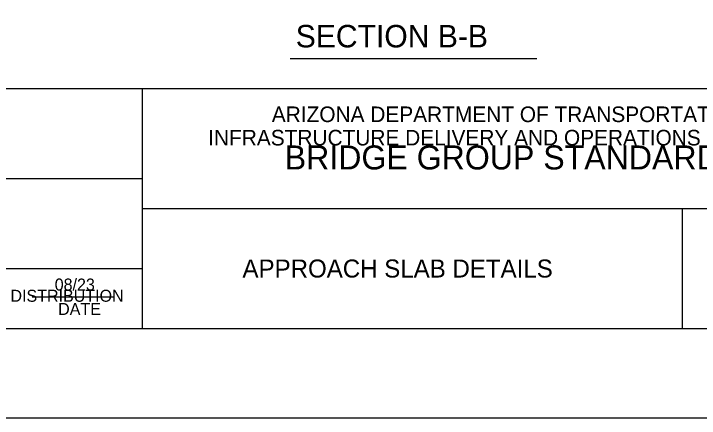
# Model space of a CAD drawing. Extents: x 0 to 2.83, y -0.03 to 1.83.
# Drawn here: x 2.0982 to 2.5744, y 0 to 0.2812 of the extents above; entities that cross this region are included whole.
import ezdxf

# ---------------------------------------------------------------- set-up
doc = ezdxf.new("R2010")
doc.units = 0
for name, color, linetype in [('57', 7, 'Continuous'), ('62', 7, 'Continuous'), ('63', 7, 'Continuous')]:
    doc.layers.add(name, color=color, linetype=linetype)

msp = doc.modelspace()

# ---------------------------------------------------------------- linework, layer by layer
at = {"layer": '57'}
msp.add_line((2.29027, 0.25017), (2.4616, 0.25017), dxfattribs=at)
at = {"layer": '62'}
for p, q in [((2.72918, 0.22911), (1.85418, 0.22911)), ((2.72918, 0.22911), (1.85418, 0.22911)), ((2.72918, 0.22911), (1.85418, 0.22911)), ((2.18751, 0.22911), (2.18751, 0.06244)), ((2.18751, 0.22911), (2.18751, 0.06244)), ((2.18751, 0.22911), (2.18751, 0.06244)), ((1.85418, 0.16661), (2.18751, 0.16661)), ((2.18751, 0.14578), (2.72918, 0.14578)), ((2.56251, 0.14578), (2.56251, 0.06244)), ((2.56251, 0.14578), (2.56251, 0.06244)), ((2.56251, 0.14578), (2.56251, 0.06244)), ((1.85418, 0.10411), (2.18751, 0.10411)), ((2.11099, 0.08432), (2.16752, 0.08432)), ((2.11099, 0.08432), (2.16752, 0.08432)), ((2.11099, 0.08432), (2.16752, 0.08432))]:
    msp.add_line(p, q, dxfattribs=at)
msp.add_lwpolyline([(2.72918, 1.77077), (0.10418, 1.77077), (0.10418, 0.06244), (2.72918, 0.06244)], close=True, dxfattribs=at)
at = {"layer": '63'}
for p, q in [((1.85418, 0.16661), (2.18751, 0.16661)), ((1.85418, 0.16661), (2.18751, 0.16661)), ((2.18751, 0.14578), (2.72918, 0.14578)), ((2.18751, 0.14578), (2.72918, 0.14578)), ((1.85418, 0.10411), (2.18751, 0.10411)), ((1.85418, 0.10411), (2.18751, 0.10411)), ((2.83333, 0), (0, 0)), ((2.83333, 0), (0, 0)), ((2.83333, 0), (0, 0))]:
    msp.add_line(p, q, dxfattribs=at)
msp.add_lwpolyline([(2.72918, 1.77077), (0.10418, 1.77077), (0.10418, 0.06244), (2.72918, 0.06244)], close=True, dxfattribs=at)

# ---------------------------------------------------------------- texts
at = {"layer": '57'}
msp.add_text('SECTION B-B', height=0.015625, dxfattribs=at).set_placement((2.29407, 0.25782))
at = {"layer": '62'}
for s, height, p in [('ARIZONA DEPARTMENT OF TRANSPORTATION', 0.0108333, (2.27746, 0.20591)), ('INFRASTRUCTURE DELIVERY AND OPERATIONS DIVISION', 0.0108333, (2.23327, 0.18966)), ('BRIDGE GROUP STANDARD DRAWING', 0.0166667, (2.28645, 0.17299)), ('APPROACH SLAB DETAILS', 0.0125, (2.25709, 0.09786)), ('08/23', 0.008333, (2.12667, 0.08882)), ('STANDARDS COMMITTEE APPROVED FOR DISTRIBUTION', 0.0083333, (1.86251, 0.081)), ('DATE', 0.008333, (2.12904, 0.07182))]:
    msp.add_text(s, height=height, dxfattribs=at).set_placement(p)

doc.saveas('drawing.dxf')
